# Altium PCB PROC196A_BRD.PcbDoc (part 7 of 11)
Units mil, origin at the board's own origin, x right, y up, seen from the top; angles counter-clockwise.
Board outline 3346.45 x 4921.26 mil, 8 copper layers (Top Layer, GND1, SIG1, PWR1, PWR2, SIG2, GND2, Bottom Layer), stack 54.534 mil thick; 736 components, 498 nets, 3030 pads, 1279 vias.
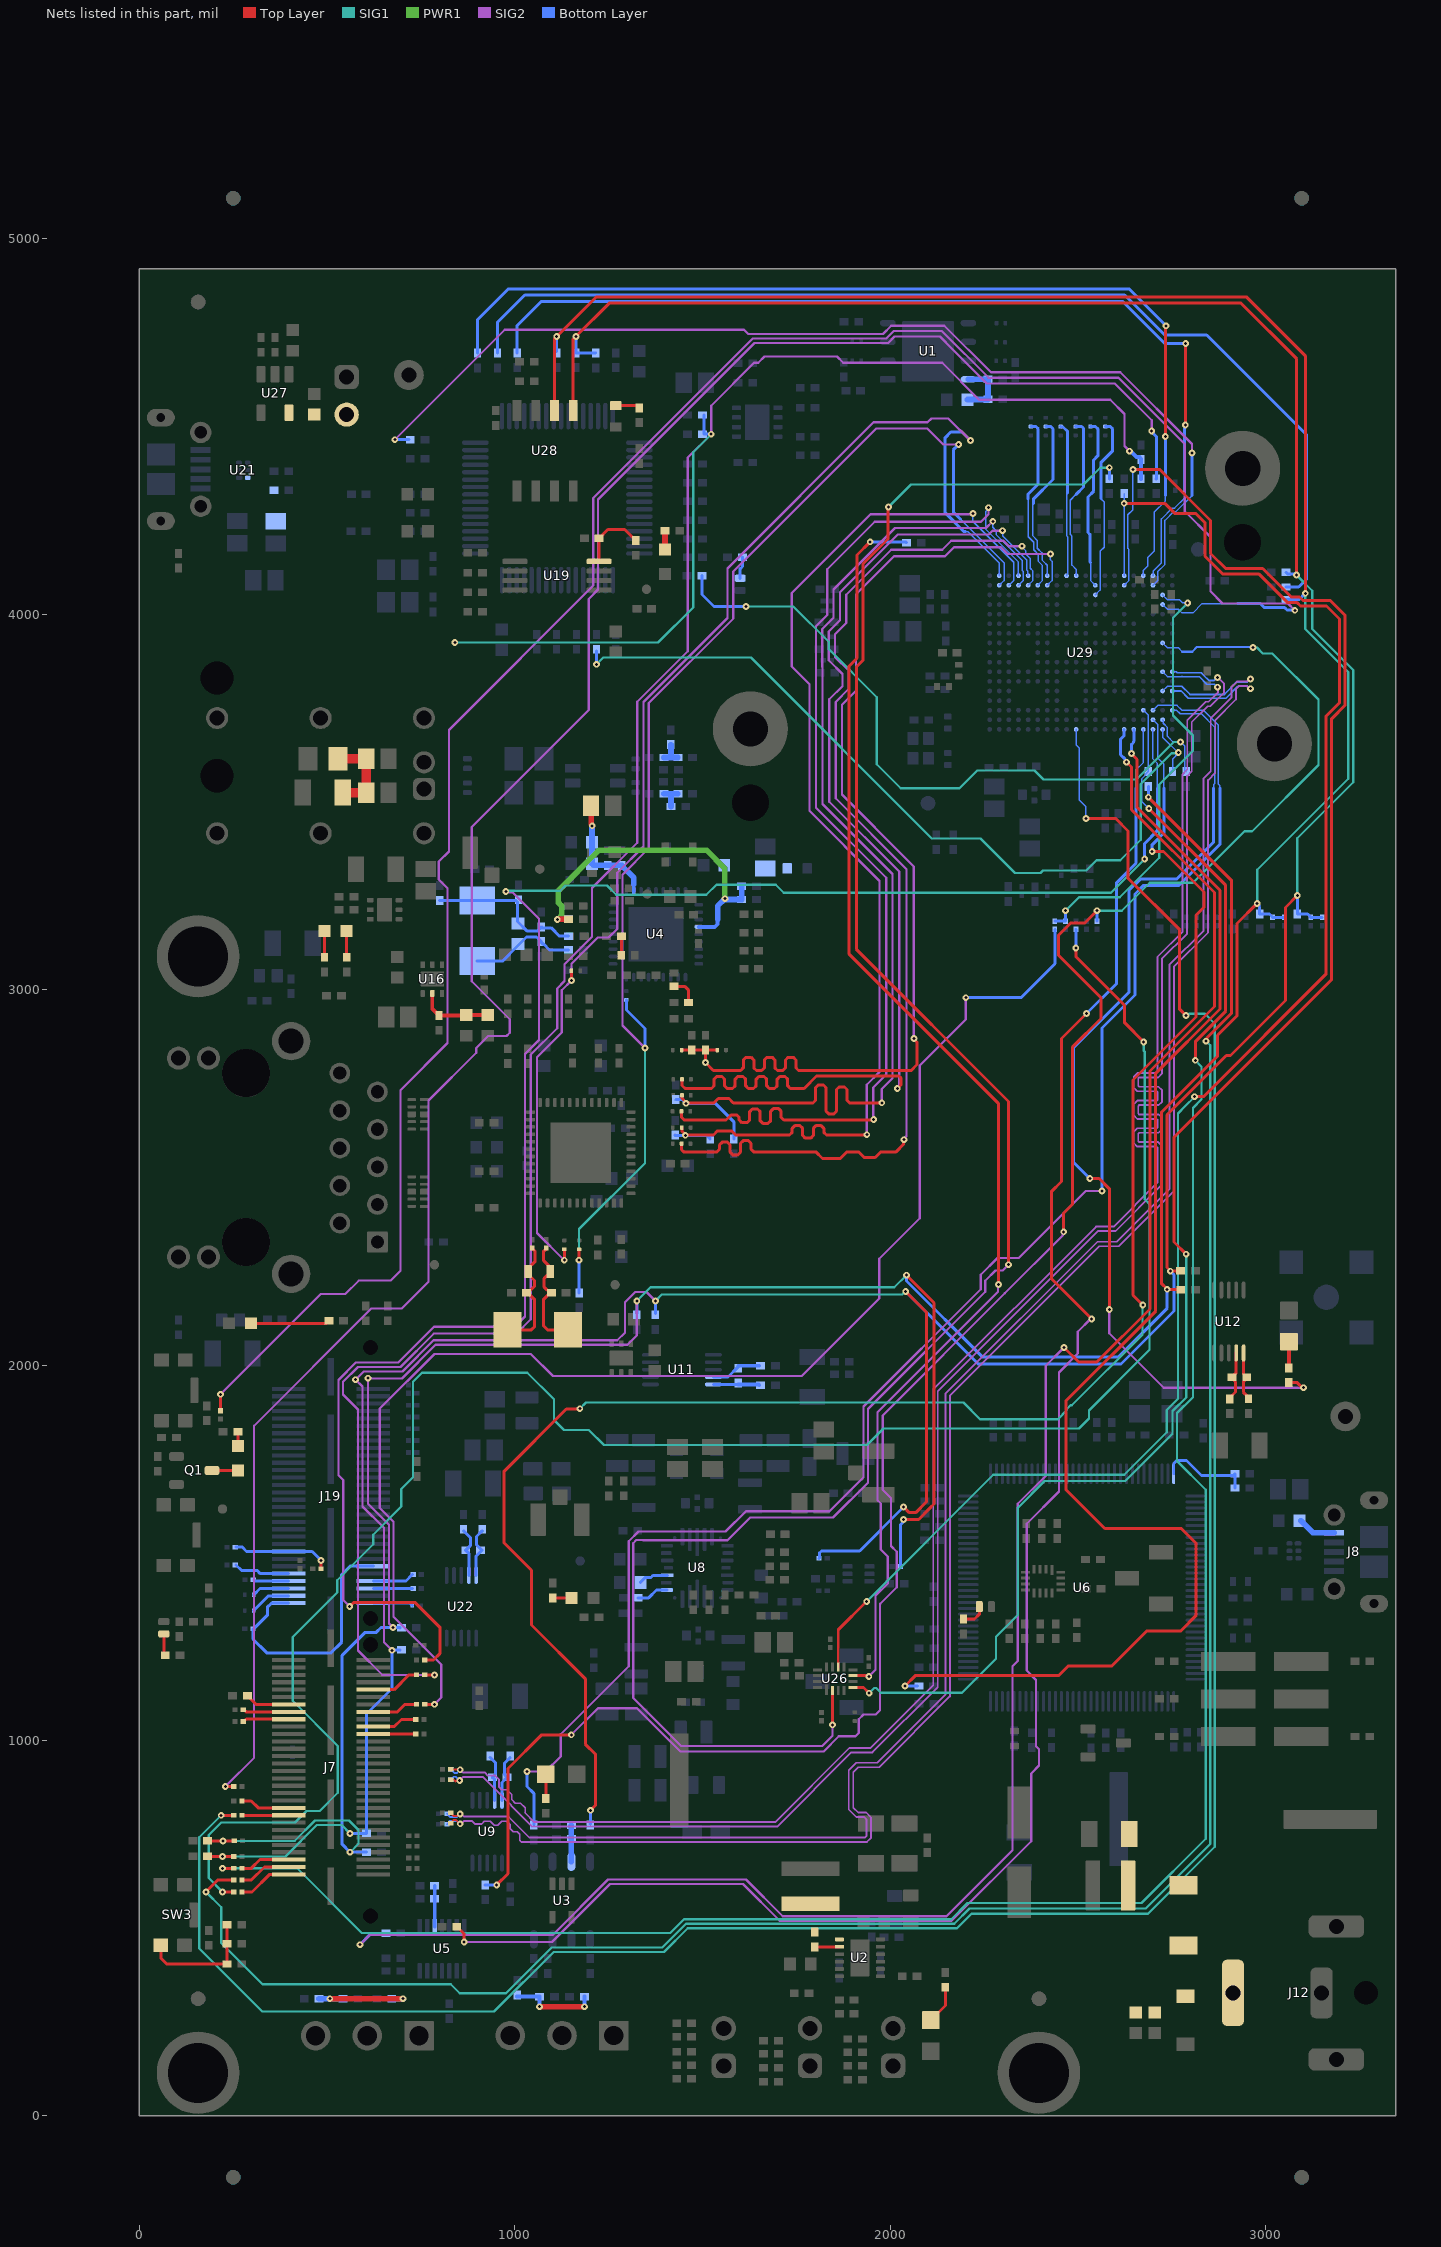
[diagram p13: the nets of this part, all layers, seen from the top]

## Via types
v1: diameter 18, hole 8, Top Layer to Bottom Layer, tented both sides, 1230 vias
v2: diameter 19.68, hole 7.87, Top Layer to Bottom Layer, 30 vias
v3: diameter 20, hole 10, Top Layer to Bottom Layer, tented both sides, 11 vias
v4: diameter 10, hole 4, SIG2 to Bottom Layer, tented both sides, 6 vias
v5: diameter 19.68, hole 7.87, Top Layer to Bottom Layer, tented both sides, 2 vias

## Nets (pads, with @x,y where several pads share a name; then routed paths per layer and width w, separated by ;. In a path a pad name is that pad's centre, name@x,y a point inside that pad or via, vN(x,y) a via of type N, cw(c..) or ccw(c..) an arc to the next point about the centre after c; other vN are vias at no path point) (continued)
LVDS_TX2_CLK_N: R349.2 R361.2 U29.E20 | length 5089.8
  Top Layer w4.8: R361.2@829.54,779.34 830.33,779.34 834.23,783.24 834.23,785.43 837.04,788.24 842.74,788.24 853.17,777.81 v1(854.61,777.81)
  SIG2 w4.8: v1(854.61,777.81) 857.02,777.81 864.21,785 886.91,785 894.91,777 911.52,777 919.33,784.81 935.08,784.81 945.69,774.21 954.77,774.21 965.37,784.81 978.7,784.81 987.74,775.78 987.74,764.91 995.65,757 1006.52,757 1013.22,750.3 1013.22,733.85 1017.57,729.5 1938.36,729.5 1948.79,739.94 1948.79,795.24 1936.03,808 1915.02,808 1902.02,821 1902.02,915.58 1915.13,928.7 1970.76,928.7 2159.35,1117.29 2159.35,1918.25 2557.5,2316.4 2609.02,2316.4 2756.03,2463.41 2756.03,3061.48 2847.08,3152.53 2847.08,3558.45 2866.22,3577.59 2866.22,3718.14 2921.29,3773.21 2921.29,3800.97 2929.15,3808.83 2950.62,3808.83 2957.62,3801.83 v1(2960.03,3801.83)
  Bottom Layer w4.8: R349.2@819.54,776.9 820.33,776.9 824.23,780.79 824.23,782.98 827.04,785.8 833.83,785.8 833.91,785.71 845.2,785.71 853.1,777.81 v1(854.61,777.81) ; U29.E20@2751.52,3795.89 2775.23,3795.89 2794.85,3776.27 2894.78,3776.27 2925.19,3806.67 2928.25,3809.73 2950.62,3809.73 2958.52,3801.83 v1(2960.03,3801.83)
LVDS_TX2_CLK_P: R345.2 R351.2 U29.E19 | length 5088.2
  Top Layer w4.8: R351.2@829.54,807.34 830.33,807.34 834.23,803.44 834.23,801.25 837.04,798.44 845.66,798.44 851.04,803.81 v1(854.61,803.81)
  SIG2 w4.8: v1(854.61,803.81) 857.66,803.81 864.02,797.45 983.04,797.45 1038.99,741.5 1933.39,741.5 1936.79,744.91 1936.79,790.27 1931.06,796 1910.05,796 1890.02,816.03 1890.02,920.55 1910.16,940.7 1965.79,940.7 2147.35,1122.26 2147.35,1923.22 2552.53,2328.4 2604.05,2328.4 2744.03,2468.38 2744.03,3066.45 2835.08,3157.5 2835.08,3563.42 2854.22,3582.56 2854.22,3723.11 2909.29,3778.18 2909.29,3805.94 2924.18,3820.83 2950.62,3820.83 2957.62,3827.83 v1(2960.03,3827.83)
  Bottom Layer w4: U29.E19@2725.93,3795.89 2738.65,3808.61 2763.22,3808.61
  Bottom Layer w4.8: R345.2@819.54,804.9 820.33,804.9 824.23,801 824.23,798.81 827.04,796 838.05,796 838.13,795.91 845.2,795.91 853.1,803.81 v1(854.61,803.81) ; 2763.22,3808.61 2776.93,3808.61 2799.07,3786.47 2890.56,3786.47 2924.03,3819.93 2925.19,3819.93 2950.62,3819.93 2958.52,3827.83 v1(2960.03,3827.83)
LVDS_TX3_FRCLK_N: R323.2 R341.2 U29.G20 | length 5061.1
  Top Layer w4.8: R341.2@832.81,891.74 837,895.93 841.82,891.11 841.97,891.11 842.48,890.59 845.12,893.23 v1(853.37,893.23)
  SIG2 w4.8: v1(853.37,893.23) 863.07,902.93 914.79,902.93 934.37,883.35 1047.12,770.6 1699.34,770.6 1896.74,968 1952.98,968 2127.14,1142.16 2127.14,1930.44 2553.7,2357 2600.41,2357 2724.02,2480.61 2724.02,2573.34 2724.02,2584.23 2714.18,2594.07 2663.42,2594.07 2660.94,2596.55 2660.94,2616.39 2663.42,2618.87 2715.12,2618.87 2724.63,2628.38 2724.63,2658.16 2715.12,2667.67 2663.42,2667.67 2660.94,2670.15 2660.94,2689.99 2663.42,2692.47 2715.12,2692.47 2724.63,2701.98 2724.63,2731.76 2715.12,2741.27 2663.42,2741.27 2660.94,2743.75 2660.94,2763.59 2663.42,2766.07 2714.18,2766.07 2724.02,2775.91 2724.02,2796 2724.02,3082.12 2791.23,3149.33 2791.23,3569.02 2803.83,3581.62 2803.83,3713.21 2845.73,3755.11 2853.22,3755.11 2889.89,3791.78 2889.89,3814.6 v1(2872.49,3832)
  Bottom Layer w4.8: R323.2@829.54,895.01 837.76,903.22 843.38,903.22 v1(853.37,893.23) ; U29.G20@2751.52,3847.07 2762.19,3847.07 2764.98,3844.27 2828.62,3844.27 2834.89,3838 2848.79,3824.1 2863.08,3824.1 2870.98,3832 v1(2872.49,3832) v1@2871.96,3831.47
LVDS_TX3_FRCLK_P: R322.2 R327.2 U29.G19 | length 5062.3
  Top Layer w4.8: R327.2@829.46,922.93 830.25,922.93 830.75,922.43 854.11,922.43 v1(854.61,921.93)
  SIG2 w4.8: v1(854.61,921.93) 861.61,914.93 899.66,914.93 919.76,914.93 928.33,906.35 947.63,906.35 957.71,896.27 957.71,876.98 965.95,868.73 979.37,868.73 992.1,856 992.1,842.79 992,842.69 1001.82,832.87 1015.32,832.87 1027.86,820.33 1027.86,807.78 1027.38,807.3 1052.09,782.6 1694.37,782.6 1891.77,980 1948.01,980 2115.14,1147.13 2115.14,1935.41 2548.73,2369 2595.44,2369 2712.02,2485.58 2712.02,2573.34 2712.02,2579.26 2709.21,2582.07 2658.45,2582.07 2648.94,2591.58 2648.94,2621.36 2658.45,2630.87 2710.15,2630.87 2712.63,2633.35 2712.63,2653.19 2710.15,2655.67 2658.45,2655.67 2648.94,2665.18 2648.94,2694.96 2658.45,2704.47 2710.15,2704.47 2712.63,2706.95 2712.63,2726.79 2710.15,2729.27 2658.45,2729.27 2648.94,2738.78 2648.94,2768.56 2658.45,2778.07 2709.21,2778.07 2712.02,2780.88 2712.02,2796 2712.02,3087.09 2779.23,3154.3 2779.23,3573.99 2791.83,3586.59 2791.83,3718.18 2840.76,3767.11 2848.25,3767.11 2873.75,3792.61 2873.75,3804.74 v1(2872.49,3806)
  Bottom Layer w4: U29.G19@2725.93,3847.07 2738.8,3834.2 2777.55,3834.2 2777.67,3834.07
  Bottom Layer w4.8: R322.2@829.46,922.93 838.96,913.42 846.11,913.42 v1(854.61,921.93) ; 2777.67,3834.07 2778.07,3833.67 2824.22,3833.67 2844,3813.9 2863.08,3813.9 2870.98,3806 v1(2872.49,3806)
MCU_CLK_OUT: R165.1 R216.1 U29.R19 | length 1198.4
  SIG1 w6: v1(2467,3210.52) 2503.1,3246.62 2611.96,3246.62 2717.05,3351.71 2717.05,3536.81 2717.05,3546.92 2806.96,3636.83 2806.96,3676.99 2777.67,3706.28 2753.57,3730.38 2753.57,3991.05 v1(2792.89,4030.37)
  Bottom Layer w4: U29.R19@2725.93,4051.79 2738.76,4038.96 2770.86,4038.96 2779.45,4030.37 v1(2792.89,4030.37) v1@2796.89,4030.37
  Bottom Layer w8: R165.1@2439,3182.81 R216.1@2467,3182.81 v1(2467,3210.52)
MCU_CLKOUT: R115.1 R165.2 | length 3653.8
  Top Layer w8: R115.1@760.24,1096.36 v1(786.39,1096.36)
  SIG2 w6: v1(786.39,1096.36) 804.39,1114.36 804.39,1202.13 677.21,1329.31 677.21,1582.74 640.44,1619.51 640.44,1884.22 786.03,2029.81 1043,2029.81 1102,1970.81 1764.81,1970.81 1971.14,2177.14 1971.14,2282.99 2079,2390.85 2079,2798 2201.8,2920.8 v1(2201.8,2978.71)
  Bottom Layer w8: v1(2201.8,2978.71) 2348.61,2978.71 2439.12,3069.22 2439.12,3160.64 R165.2@2439,3160.76
MIPI_DBG_DETECT: J19.15 R226.2 R321.2 | length 263.6
  Top Layer w8: R226.2@484,1457.42 v1@484,1479.65
  Bottom Layer w8: R321.2@257.44,1514.71 274.46,1514.71 285.68,1503.49 J19.15@397.49,1503.49 460.54,1503.49 484.04,1479.99 v1(484.04,1479.68)
MIPI_JTAG_NRST: J19.9 R508.2 | length 149.7
  Bottom Layer w8: R508.2@257.44,1467.61 271.89,1453.16 313.33,1453.16 322.05,1444.44 J19.9@397.49,1444.44
MIPI_NRST: J19.6 R243.1 | length 104.2
  Bottom Layer w8: J19.6@623.08,1405.07 R243.1@727.27,1405.07
MIPI_RTCK: J19.7 R244.2 | length 93.1
  Bottom Layer w8: R244.2@305.65,1427.81 308.71,1424.75 J19.7@397.49,1424.75
MIPI_TCK: J19.3 R375.1 | length 109.2
  Bottom Layer w8: R375.1@304.64,1346.03 343.99,1385.38 J19.3@397.49,1385.38
MIPI_TDI: J19.5 R376.1 | length 99.9
  Bottom Layer w8: R376.1@304.64,1388.1 321.61,1405.07 J19.5@397.49,1405.07
MIPI_TMS: J19.2 R374.2 | length 106.6
  Bottom Layer w8: J19.2@623.08,1365.7 720.99,1365.7 R374.2@727.13,1359.56
MIPI_TRSTPD: J19.8 R512.1 | length 111.3
  Bottom Layer w8: J19.8@623.08,1424.75 710.12,1424.75 R512.1@727.3,1441.92
MIPI_VREF_DEBUG: J19.1 J19.12 R503.2 | length 697.2
  Bottom Layer w8: R503.2@302.91,1297.35 302.91,1269.88 339.35,1233.45 510.58,1233.45 538.82,1261.69 538.82,1441.67 561.27,1464.12 J19.12@623.08,1464.12 ; R503.2@304.88,1297.35 340.93,1333.4 340.93,1354.85 351.78,1365.7 J19.1@397.49,1365.7
MSS_EPWMA0: R81.1 U29.A18 | length 4905.5
  Top Layer w8: v1(560.23,1356.92) 570.31,1367 735.25,1367 800.49,1301.76 800.49,1231.06 783.47,1214.04 R81.1@760.24,1214.04
  SIG1 w6: v1(976.32,3261.66) 978.57,3263.91 1121.09,3263.91 1135,3277.81 1245.53,3277.81 1270.53,3252.81 1510.27,3252.81 1537.27,3279.81 1695.53,3279.81 1716.72,3258.62 2588.39,3258.62 v1(2678.14,3348.37)
  SIG2 w6: v1(560.23,1356.92) 543.27,1373.88 543.27,1694.04 530.65,1706.66 530.65,1960.46 577.39,2007.2 690.57,2007.2 785.18,2101.81 999.8,2101.81 1027.57,2129.58 1027.57,2828.76 1064.65,2865.85 1064.65,3189.19 994.32,3259.52 978.46,3259.52 v1(976.32,3261.66)
  Bottom Layer w4: U29.A18@2700.34,3693.52 2700.34,3614.66 2712,3603 2712,3536.81
  Bottom Layer w8: v1(2678.14,3348.37) 2678.14,3389.57 2712,3423.43 2712,3536.81
MSS_EPWMA1: R198.1 R213.2 | length 6034.8
  Top Layer w8: v1(177.19,596.46) 208.69,627.95 R198.1@249.35,627.95 ; v1(2688,3512.81) 2909,3291.81 2909,2936.45 2843.77,2871.22 2843.77,2864.91 v1(2841.86,2863)
  SIG1 w6: v1(177.19,596.46) 218.08,555.57 218.08,460.07 327.93,350.23 829.72,350.23 853.17,326.77 976.78,326.77 1098.68,448.66 1392.94,448.66 1456.12,511.84 2170.88,511.84 2211.54,552.5 2681.26,552.5 2853,724.24 2853,1010.67 2853,1639.81 2853,2851.86 v1(2841.86,2863)
  Bottom Layer w8: R213.2@2687.85,3541.71 2687.93,3541.64 2687.93,3512.88 v1(2688,3512.81)
MSS_EPWMB0: R197.1 R213.1 U29.C17 | length 6033.5
  Top Layer w8: v1(221.63,659.45) R197.1@249.35,659.45 ; v1(2689.2,3483.04) 2894,3278.24 2894,2942.66 2813,2861.66 v1(2813,2812)
  SIG1 w6: v1(221.63,659.45) 420.3,659.45 592.48,487.27 1414.58,487.27 1451.15,523.84 2163.26,523.84 2206.14,566.72 2669.95,566.72 2841,737.78 2841,1667.97 2764.58,1744.4 2764.58,1872.39 2806.68,1914.49 2806.68,2684.94 2829.28,2707.54 2829.28,2795.72 v1(2813,2812)
  Bottom Layer w4: U29.C17@2674.75,3744.7 2687.62,3731.83 2687.62,3581.32 R213.1@2687.85,3581.08 2680.77,3574 2680.77,3572.03 2670.01,3561.27 2670.01,3502.23 v1(2689.2,3483.04)
MSS_GPIO_1: R329.1 U29.A10 | length 6580.9
  Top Layer w8: v1(218.08,800.66) R329.1@249.37,800.66 ; v1(2521.67,3456) 2600.92,3456 2634.06,3422.86 2634.06,3296.84 2771.32,3159.58 2771.32,2947.8 v1(2788.12,2931)
  SIG1 w6: v1(218.08,800.66) 159.19,741.77 159.19,445.88 327.12,277.95 944.93,277.95 1103.65,436.66 1397.91,436.66 1461.09,499.84 2178.53,499.84 2216.87,538.18 2686.86,538.18 2865.17,716.49 2865.17,2909.64 2838.81,2936 2796.37,2936 2791.37,2931 v1(2788.12,2931)
  Bottom Layer w4: U29.A10@2495.62,3693.52 2495.62,3652.72 2504.17,3644.17 2504.17,3505.11 2521.67,3487.61 v1(2521.67,3456)
MSS_GPIO_2: R347.2 U29.C20 | length 2634.5
  Top Layer w8: v1(2531.9,2497) 2557.06,2497 2584.1,2469.96 v1(2584.1,2148) ; R347.2@3062.49,1953.11 3085,1953.11 3098.29,1939.81 v1(3101,1939.81)
  SIG2 w6: v1(2584.1,2148) 2584.1,2084.71 2729,1939.81 v1(3101,1939.81)
  Bottom Layer w4: U29.C20@2751.52,3744.7 2763.11,3744.7 2772.81,3735 2777.67,3735 2829.71,3735 2864.45,3700.26 2864.45,3549.11 2861.95,3546.61 2861.95,3536.81
  Bottom Layer w8: v1(2531.9,2497) 2488.17,2540.73 2488.17,2844.7 2636.1,2992.64 2636.1,3264.07 2666.54,3294.51 2762.75,3294.51 2861.95,3393.71 2861.95,3536.81
MSS_GPIO_3: R114.1 R219.2 | length 5266.8
  Top Layer w8: v1(221.63,596.46) R114.1@249.35,596.46 ; v1(2494.71,3111.3) 2494.71,3088.18 2624.94,2957.95 2624.94,2911.8 v1(2675.74,2861)
  SIG1 w6: v1(221.63,596.46) 184.83,633.25 184.83,748.37 217.97,781.51 414.72,781.51 445.4,812.19 480.49,812.19 528.78,860.48 528.78,985.24 408.37,1105.66 408.37,1275.73 526.92,1394.28 526.92,1426.72 623.02,1522.82 623.02,1548.18 698,1623.16 698,1670.15 728.99,1701.14 728.99,1955.8 753,1979.81 1033.6,1979.81 1104.72,1908.69 1104.72,1853.92 1131.32,1827.31 1197.39,1827.31 1237.7,1787 1938.73,1787 1982.62,1830.89 2503.07,1830.89 2529.6,1857.41 2529.6,1879.01 2691.33,2040.74 2691.33,2429.21 2678.7,2441.84 2678.7,2834.5 2675.74,2837.46 v1(2675.74,2861)
  Bottom Layer w8: v1(2494.71,3111.3) 2494.86,3111.44 2494.86,3160.62 R219.2@2495,3160.76
MSS_GPIO_11: R54.1 R236.2 U29.K19 | length 5482.2
  Top Layer w8: v1(951.98,615.22) 981.93,645.17 981.93,924.98 1071.95,1015 v1(1150.85,1015) ; v1(2462.42,2354.97) 2462.42,2405.08 2486.49,2429.15 2486.49,2847.78 2561.84,2923.13 2561.84,2978.63 2449.11,3091.35 2449.11,3144.27 2449.11,3145.97 2480.41,3177.26 2517.74,3177.26 v1(2551,3210.52)
  SIG1 w6: v1(2551,3210.52) 2616.99,3210.52 2691.47,3285 2807.18,3285 2944.33,3422.15 2964.46,3422.15 3141.04,3598.73 3141.04,3773.23 3018.42,3895.85 2993.02,3895.85 2977.49,3911.38 2967.23,3911.38 v1(2966.61,3912)
  SIG2 w6: v1(1150.85,1015) 1221.85,1086 1325.78,1086 1441.08,970.7 1823.23,970.7 1863.53,1011 1907.77,1011 1916.56,1019.79 1916.56,1056.28 1929.28,1069 1961.99,1069 1973.39,1080.4 1973.39,1364.43 1973.6,1364.43 2017.6,1408.44 2017.6,1502.36 2002.22,1517.75 2002.22,1645.35 1980.21,1667.36 1980.21,1865.57 2305.68,2191.04 2460.12,2345.48 2460.12,2352.68 v1(2462.42,2354.97)
  Bottom Layer w4: U29.K19@2725.93,3923.84 2738.76,3911.01 2744.66,3911.01 2767.95,3911.01 2777.67,3901.29
  Bottom Layer w6: 2777.67,3901.29 2778.46,3900.49 2804.73,3900.49 2817.24,3913 2965.61,3913 v1(2966.61,3912)
  Bottom Layer w8: R54.1@921.27,615.22 v1(951.98,615.22) ; R236.2@2551,3182.81 v1(2551,3210.52)
MSS_GPIO_28: R334.2 U29.P19 | length 5881.1
  Top Layer w8: R334.2@215.95,1878.47 216.06,1878.58 216.06,1922 v1(216.17,1922.12)
  SIG2 w6: v1(216.17,1922.12) 483.34,2189.29 548.64,2189.29 584.35,2225 669.01,2225 696,2251.99 696,2732.85 821.08,2857.93 821.08,3270.35 797.69,3293.74 797.69,3341.52 824.62,3368.45 824.62,3692.2 1209,4076.58 1209,4309.85 1634.01,4734.86 1989.89,4734.86 2010.03,4755 2137.81,4755 2262.5,4630.31 2608.64,4630.31 2785,4453.95 2785,4274.75 2853.39,4206.36 2853.39,4061.42 2885.6,4029.21 3059.86,4029.21 v1(3078.26,4010.81)
  Bottom Layer w4: U29.P19@2725.93,4026.2 2738.8,4013.33 2767.9,4013.33 2777.36,4003.87 2806.57,4003.87 2831.3,4028.6 2925.19,4028.6
  Bottom Layer w7.61: 3037.57,4018.1 3050.92,4018.1 3051.12,4017.91
  Bottom Layer w8: 2925.19,4028.6 2986.62,4028.6 2997.31,4017.91 3031.13,4017.91 3031.32,4018.1 3037.57,4018.1 ; 3051.12,4017.91 3057.26,4011.76 3077.31,4011.76 v1(3078.26,4010.81)
MSS_I2CA_SCL: R3.1 R23.2 R27.2 R33.2 R57.2 R58.2 R148.2 R229.1 R231.2 R276.1 R318.1 R390.1 U28.6 | length 10666.3
  Top Layer w8: R276.1@185.75,732.43 v1(222.91,732.43) R390.1@250.63,732.43 ; U28.6@1105.83,4543.13 1105.83,4734.27 v1(1111.81,4740.26) 1216.36,4844.81 2950.19,4844.81 3106.27,4688.73 v1(3106.27,4056) ; v1(2036,1588.81) 2076,1588.81 2107,1619.81 2117,1629.81 2117,2165.81 v1(2043.48,2239.33) ; R58.2@2774.48,2200.17 2773.57,2201.09 2739.18,2201.09 2722.42,2217.85 2722.42,2672.81 2872.27,2822.66 2872.27,2878.5 2924.16,2930.39 2924.16,3176.2 v1(2977.96,3230)
  SIG1 w6: v1(222.91,732.43) 413.73,732.43 467.77,786.47 558.52,786.47 583.89,761.1 583.89,724.54 v1@561.51,702.16 ; v1(1325.38,2170.91) 1361.55,2207.07 2011.22,2207.07 v1(2043.48,2239.33) ; v1(2977.96,3230) 2977.96,3319.4 3220.87,3562.31 3220.87,3846.18 3106.27,3960.78 v1(3106.27,4056)
  SIG2 w6: v1(675.87,1300.65) 665.21,1311.31 665.21,1574.6 609.21,1630.6 v1(609.21,1965.2) 610.25,1964.16 699.41,1964.16 789.2,2053.95 1300.14,2053.95 1325,2078.81 1325,2170.53 v1(1325.38,2170.91)
  Bottom Layer w8: R27.2@605.2,702.16 561.41,702.16 540.27,723.3 540.27,1226.73 601.64,1288.1 631.17,1288.1 643.72,1300.65 v1(675.87,1300.65) 676.09,1300.43 693.96,1300.43 R57.2@694.18,1300.21 ; R148.2@1111.81,4700.64 v1(1111.81,4740.26) ; R33.2@1325.38,2137.94 v1(1325.38,2170.91) ; R318.1@2027.72,1463.53 2027.72,1574.9 2034.14,1581.33 2034.14,1586.95 v1(2036,1588.81) ; v1(2043.48,2239.33) 2043.48,2224.22 2245.7,2022 2608.54,2022 2738.27,2151.73 v1(2738.27,2202) ; v1(2977.96,3230) 2977.96,3227.62 2984.64,3220.94 2984.64,3201.81 R23.2@2984.98,3201.47 3011.03,3201.47 3018.9,3193.6 R229.1@3018.9,3192.81 R231.2@3050,3192.81 ; R3.1@3054.13,4038.75 3055.23,4039.85 3090.12,4039.85 v1(3106.27,4056)
  other v1: 561.37,702.16
MSS_I2CA_SDA: R22.2 R29.2 R31.1 R35.2 R59.2 R62.2 R149.2 R150.2 R224.1 R227.2 R277.1 R319.2 R391.1 U28.5 | length 10567.8
  Top Layer w8: R277.1@185.75,691.43 186.23,690.95 v1(221.63,690.95) R391.1@249.35,690.95 ; U28.5@1155.83,4543.13 1155.83,4733.2 v1(1162.88,4740.26) 1251.63,4829 2934.81,4829 3083,4680.81 v1(3083,4104.81) ; v1(2035.9,1621.85) 2036.16,1621.85 2051.19,1606.81 2068,1606.81 2096.93,1635.74 2096.93,2140.88 v1(2041.61,2196.2) ; R59.2@2774.1,2251 2773.6,2250.5 2747.1,2250.5 v1(2746.6,2250) 2746.6,2250.51 2737.42,2259.69 2737.42,2666.6 2895.85,2825.03 2906.88,2825.03 3053.15,2971.29 3053.15,3218.96 v1(3085,3250.81)
  SIG1 w6: v1(221.63,690.95) 389.22,690.95 472.74,774.47 539.1,774.47 v1(561.37,752.2) ; v1(1374.75,2170.91) 1391.75,2187.91 2032.1,2187.91 2040.39,2196.2 v1(2041.61,2196.2) ; v1(3083,4104.81) 3124.96,4062.85 3124.96,3960.73 3233.98,3851.71 3233.98,3552.69 3085,3403.71 v1(3085,3250.81)
  SIG2 w6: v1(673.26,1240.08) 651.44,1261.91 651.44,1566.37 594.33,1623.48 594.33,1942.63 v1(575.81,1961.14) 597.87,1983.2 700.83,1983.2 783.58,2065.95 1273.14,2065.95 1293.5,2086.31 1293.5,2167.31 1320.85,2194.67 1350.99,2194.67 v1(1374.75,2170.91)
  Bottom Layer w5.5: v1@561.27,752.2 v1@561.56,752.49
  Bottom Layer w8: v1@561.27,752.2 v1(561.37,752.2) 605.05,752.2 R29.2@605.34,752.49 605.34,1070.68 673.26,1138.61 v1(673.26,1240.08) 673.8,1240.62 693.64,1240.62 R62.2@694.18,1241.15 ; R149.2@1162.88,4696.7 1215.08,4696.7 R150.2@1215.81,4695.97 ; R149.2@1162.88,4700.64 v1(1162.88,4740.26) ; R35.2@1374.75,2137.94 v1(1374.75,2170.91) ; R319.2@1810.74,1485.22 1811.27,1485.75 1811.27,1499.08 1817.03,1504.84 1918.89,1504.84 v1(2035.9,1621.85) ; v1(2041.61,2196.2) 2234.81,2003 2615.29,2003 2756.27,2143.98 2756.27,2240.31 v1(2746.6,2250) ; R31.1@3054.85,4111.81 3059.03,4107.63 3077.56,4107.63 3080.38,4104.81 v1(3083,4104.81) ; v1(3085,3250.81) R22.2@3085,3201.47 3112.61,3201.47 3120.48,3193.6 R224.1@3120.48,3192.81 R227.2@3151,3192.81
MSS_MCANA_RX: R12.1 U29.B18 | length 4764.9
  Top Layer w8: v1(1173.44,1883.81) 1172.44,1882.81 1137.32,1882.81 972,1717.49 972,1526.18 1044.88,1453.3 1044.88,1307.32 1188,1164.2 1188,990.09 1215.78,962.31 1215.78,828.04 v1(1201.74,814) ; v1(2673.33,2160) 2646.98,2186.35 2646.98,2759.28 2814.88,2927.18 2814.88,3198.2 2836.11,3219.43 2836.11,3260.51 2728.64,3367.98 v1(2698.33,3367.98)
  SIG1 w6: v1(1173.44,1883.81) 1189.63,1900 2195.32,1900 2239.51,1855.81 2447.12,1855.81 2470,1878.69 2470,1882.27 2480.54,1892.81 2484.12,1892.81 2672.19,2080.88 2672.19,2158.86 v1(2673.33,2160)
  Bottom Layer w4: U29.B18@2700.34,3719.11 2713.06,3706.39 2713.06,3661.86 2713.06,3658.75 2713.06,3617.28 2729.44,3600.9 2729.44,3536.81
  Bottom Layer w8: R12.1@1200.93,776.96 1201.33,777.37 1201.33,813.59 v1(1201.74,814) ; v1(2698.33,3367.98) 2698.26,3368.05 2698.26,3386.52 2729.44,3417.7 2729.44,3536.81
MSS_MCANA_TX: R11.1 U29.C18 | length 4313.7
  SIG2 w6: v1(1032.65,917) 1082.19,917 1122.63,957.44 1122.63,1016.63 1303.44,1197.44 1303.44,1530.44 1329.5,1556.5 1561.5,1556.5 1615.85,1610.85 1838.29,1610.85 1928.84,1701.4 1928.84,1889.35 2241.37,2201.88 2241.37,2240.45 2286.32,2285.4 2342.92,2285.4 2521.52,2464 v1(2564.6,2464)
  Bottom Layer w4: U29.C18@2700.34,3744.7 2713.06,3757.43 2764.38,3757.43 2777.31,3744.5 2834.59,3744.5 2874.25,3704.84 2874.25,3547.9 2878.25,3543.9 2878.25,3536.81
  Bottom Layer w8: v1(1032.65,917) 1032.65,877.54 1050.93,859.26 R11.1@1050.93,774.4 ; v1(2564.6,2464) 2564.6,2898.08 2652.4,2985.88 2652.4,3254.96 2675.65,3278.21 2769.5,3278.21 2878.25,3386.96 2878.25,3536.81
MSS_MCANB_RX: R25.1 U29.A17 | length 4957
  Top Layer w8: R25.1@845.68,503.91 847.64,503.91 853.49,498.07 853.49,496.1 865.4,484.19 v1(865.4,463.27) ; v1(2523.36,2936.68) 2456.49,2869.82 2456.49,2488.84 2429.42,2461.77 2429.42,2230.47 v1(2537.05,2122.85)
  SIG2 w6: v1(865.4,463.27) 1099.49,463.27 1253.75,617.54 1608.09,617.54 1706.29,519.33 2163.52,519.33 2375.74,731.55 2375.74,911.78 2397,933.03 2397,976.47 2388.98,984.49 2388.98,1161.33 2363.93,1186.38 2363.93,1384.34 2364,1384.41 2364,1419.21 2363.93,1419.28 2363.93,1577.19 2449.74,1663.01 2449.74,1980.33 2500.25,2030.84 2500.25,2089.02 2534.07,2122.85 v1(2537.05,2122.85)
  Bottom Layer w4: 2655.3,3536.81 2655.3,3586.11 2674.75,3605.56 U29.A17@2674.75,3693.52
  Bottom Layer w8: v1(2523.36,2936.68) 2603.5,3016.82 2603.5,3285.26 2655.3,3337.06 2655.3,3536.81
MSS_MCANB_TX: R21.1 U29.A15 | length 5429.2
  Top Layer w8: v1(2463.51,2047) 2502.51,2008 2550.74,2008 2692.42,2149.68 2692.42,2783.51 2864,2955.09 2864,3258.7 2643,3479.7 2643,3536.81 2643,3593.36 v1(2630.07,3606.29)
  SIG2 w6: v1(587.53,455.73) 614.24,482.44 1101.69,482.44 1248.78,629.54 1615.8,629.54 1714,531.33 2150.02,531.33 2326.16,707.48 2326.16,1197.91 2339.93,1211.68 2339.93,1394.28 2340,1394.35 2340,1409.27 2339.93,1409.34 2339.93,1630.3 2414.4,1704.77 2414.4,1997.89 v1(2463.51,2047)
  Bottom Layer w8: v1(587.53,455.73) 618,486.19 R21.1@657.14,486.19 ; U29.A15@2623.57,3693.52 2623.57,3677.07 2613.9,3667.4 2613.9,3661.87 2613.9,3658.75 2613.9,3626.06 2625,3614.96 2625,3614.07 2630,3609.07 2630.07,3609 v1(2630.07,3606.29)
MSS_MDIO_CLK: R249.1 R369.1 U29.U2 | length 3508.9
  Top Layer w8: v1(1132.04,2279.28) R369.1@1132.04,2308.19 ; R249.1@1150.95,3050.42 1150.95,3028.46 1151.06,3028.35 v1(1151.06,3024.41)
  SIG2 w6: v1(1132.04,2279.28) 1059.46,2351.86 1059.46,2820.27 1125.2,2886.01 1125.2,2998.55 v1(1151.06,3024.41) 1151.06,3068.9 1220.97,3138.81 1250,3138.81 1273,3161.81 1273,3311.81 1343,3381.81 1343,3766.6 1566.58,3990.18 1566.58,4122.41 1955.98,4511.81 2099.88,4511.81 2110.07,4522 2155,4522 v1(2214,4463)
  Bottom Layer w4: 2201,4220.31 2207.54,4220.31 2290.89,4136.96 U29.U2@2290.89,4102.97
  Bottom Layer w8: 2201,4220.31 2197,4220.31 2146.85,4270.47 2146.85,4387.18 2146.85,4470.8 2161.59,4485.55 2191.45,4485.55 v1(2214,4463)
MSS_MDIO_DATA: R247.1 R280.1 R413.1 U29.T2 | length 3536.5
  Top Layer w8: v1(1171.49,2279.28) R413.1@1171.49,2308.19
  SIG1 w6: v1(1171.49,2279.28) 1171.49,2362.46 1346.93,2537.89 v1(1346.93,2845.01)
  SIG2 w6: v1(1346.93,2845.01) 1287,2904.94 1287,3306.61 1357.07,3376.68 1357.07,3763.7 1582,3988.63 1582,4113.9 1963.1,4495 2099.01,4495 2141.53,4452.49 v1(2182.59,4452.49)
  Bottom Layer w4: 2187.74,4253.55 2303.61,4137.67 2303.61,4090.1 U29.T2@2290.89,4077.38
  Bottom Layer w8: R280.1@1171.49,2192.39 v1(1171.49,2279.28) ; R247.1@1297.46,2972.72 1297.46,2947.46 1297.67,2947.25 1297.67,2946.07 1346.93,2896.81 v1(1346.93,2845.01) ; v1(2182.59,4452.49) 2168.57,4438.47 2168.57,4387.18 2168.57,4272.72 2187.74,4253.55
MSS_RGMII_RCLK: R234.1 R290.1 U29.T5 | length 2981.8
  Top Layer w8: R290.1@1444.53,2590.02 1444.53,2573.69 1450.02,2568.2 1532,2568.2 1538.56,2568.2 1545.56,2575.2 1545.56,2586.68 1552.56,2593.68 1566.56,2593.68 1573.56,2586.68 1573.56,2567.27 1580.56,2560.27 1594.56,2560.27 1601.56,2567.27 1601.56,2590.93 1608.56,2597.93 1622.56,2597.93 1629.56,2590.93 1629.56,2575.2 1636.56,2568.2 1668.56,2568.2 1802,2568.2 1819.78,2550.42 1867.22,2550.42 1885,2568.2 1915.84,2568.2 1931.04,2553 1960.36,2553 1975.56,2568.2 2016.2,2568.2 2036,2588 2036,2599.42 v1(2037.14,2600.56)
  SIG2 w6: v1(2037.14,2600.56) 2037.14,2603.51 2043.7,2610.07 2043.7,3321.11 1855,3509.81 1855,3766.48 1890,3801.48 1890,3849.43 1853.29,3886.13 1853.29,3946.97 1883.28,3976.96 1883.28,4052.1 2002.98,4171.81 2138.96,4171.81 2163.15,4196 2302.35,4196 2316.7,4181.65 v1(2351.28,4181.65)
  Bottom Layer w4: v1(2351.28,4181.65) 2351.28,4179.32 2360.73,4169.88 2360.73,4161.6 2373.28,4149.04 2373.28,4138.07 2373.28,4127.7 2373.28,4122.62 2380.38,4115.52 2380.38,4090.1 U29.T5@2367.66,4077.38
MSS_RGMII_RCTL: R195.1 R211.1 R245.1 R289.2 U29.T7 | length 2886.3
  Top Layer w8: R195.1@1444.84,2839.29 R211.1@1471.91,2839.29 R289.2@1508.33,2839.29 ; v1(1508.36,2805.87) R289.2@1508.33,2839.29 ; v1(1508.36,2805.87) 1529.2,2785.02 1598.05,2785.02 1602.05,2785.02 1609.05,2792.02 1609.05,2812.72 1616.05,2819.72 1630.05,2819.72 1637.05,2812.72 1637.05,2791.7 1644.05,2784.7 1658.05,2784.7 1665.05,2791.7 1665.05,2812.8 1672.05,2819.8 1686.05,2819.8 1693.05,2812.8 1693.05,2791.77 1700.05,2784.77 1714.05,2784.77 1721.05,2791.77 1721.05,2812.87 1728.05,2819.87 1742.05,2819.87 1749.05,2812.87 1749.05,2792.02 1756.05,2785.02 1885.73,2785.02 2056.42,2785.02 2071.94,2800.54 2071.94,2860.31 2063.58,2868.67 v1(2063.58,2870) ; R245.1@1539.21,2839.29 R289.2@1508.33,2839.29
  SIG2 w6: v1(2063.58,2870) 2063.25,2870.33 2063.25,3323.56 2063.25,3328.56 2050,3341.81 1872,3519.81 1872,3759.44 1909,3796.44 1909,4053.28 2010.53,4154.81 2146,4154.81 2170.19,4179 2295.31,4179 2313.31,4161 v1(2427,4161)
  Bottom Layer w4: U29.T7@2418.84,4077.38 2431.6,4090.14 2431.6,4127.7 2431.6,4141.1 2427,4145.71 v1(2427,4161)
MSS_RGMII_RD0: R173.1 R237.1 R287.2 R325.1 U29.T3 | length 3065.5
  Top Layer w8: R325.1@1444.84,2632.81 1445.22,2632.43 1445.22,2623.41 1454.58,2614.04 v1(1454.58,2612.04) ; v1@1455.47,2612.93 1529.26,2612.93 1540.33,2624 1577.49,2624 1588.57,2612.93 1728.28,2612.93 1732.28,2612.93 1739.28,2619.93 1739.28,2630.81 1746.28,2637.81 1760.28,2637.81 1767.28,2630.81 1767.28,2611.37 1774.28,2604.37 1788.28,2604.37 1795.28,2611.37 1795.28,2630.81 1802.28,2637.81 1816.28,2637.81 1823.28,2630.81 1823.28,2619.93 1830.28,2612.93 1888,2612.93 1937.12,2612.93 v1(1938,2613.81)
  SIG2 w6: v1(1938,2613.81) 1938,2746.64 1971.98,2780.62 1971.98,3289.87 1785.29,3476.56 1785.29,3813.57 1738.05,3860.81 1738.05,4056.86 1948,4266.81 2218.79,4266.81 v1(2220.79,4268.81)
  Bottom Layer w4: v1(2220.79,4268.81) 2220.17,4268.19 2220.17,4247.99 2329.2,4138.95 2329.2,4090.1 U29.T3@2316.48,4077.38
  Bottom Layer w8: R173.1@1427.4,2612.48 1427.62,2612.26 1454.36,2612.26 v1(1454.58,2612.04) 1511.68,2612.04 1520.83,2602.89 R287.2@1520.83,2602.23
MSS_RGMII_RD1: R238.1 R336.1 U29.U4 | length 2960
  Top Layer w8: R336.1@1444.11,2676.49 1444.11,2660.15 1451.46,2652.81 1553,2652.81 1563.01,2652.81 1570.01,2659.81 1577.01,2666.81 1591.01,2666.81 1598.01,2659.81 1598.01,2652.81 1605.01,2645.81 1619.01,2645.81 1626.01,2652.81 1626.01,2675.17 1633.01,2682.17 1647.01,2682.17 1654.01,2675.17 1654.01,2650.9 1661.01,2643.9 1675.01,2643.9 1682.01,2650.9 1682.01,2676.17 1689.01,2683.17 1703.01,2683.17 1710.01,2676.17 1710.01,2659.81 1717.01,2652.81 1749.01,2652.81 1954.72,2652.81 v1(1956.15,2654.24)
  SIG2 w6: v1(1956.15,2654.24) 1955,2655.38 1955,2739.32 1989.54,2773.86 1989.54,3298.27 1802.89,3484.92 1802.89,3852.65 1802.29,3853.25 1802.29,3968.1 1832.28,3998.08 1832.28,4120.29 1958.99,4247 2241.88,4247 2261.87,4266.99 v1(2261.87,4284)
  Bottom Layer w4: v1(2261.87,4284) 2261.87,4281.32 2255.21,4274.66 2255.21,4226.38 2342.07,4139.52 U29.U4@2342.07,4102.97
MSS_RGMII_RD2: R239.1 R286.1 R288.2 R338.1 U29.T4 | length 3166.2
  Top Layer w8: R338.1@1445.56,2718.89 1445.94,2718.51 1445.94,2710.12 1456.52,2699.53 v1(1456.52,2697.53) 1457.16,2698.17 1530.42,2698.17 1542.25,2710 1570.57,2710 1582.4,2698.17 1790.44,2698.17 1794.44,2698.17 1801.44,2705.17 1801.44,2739.18 1808.44,2746.18 1822.44,2746.18 1829.44,2739.18 1829.44,2676.54 1836.44,2669.54 1850.44,2669.54 1857.44,2676.54 1857.44,2733.92 1864.44,2740.92 1878.44,2740.92 1885.44,2733.92 1885.44,2705.31 1892.44,2698.31 1973.62,2698.42 1977.62,2698.43 v1(1978,2698.81)
  SIG2 w6: v1(1978,2698.81) 1978,2735.44 2006.54,2763.98 2006.54,3308.23 1819.89,3494.88 1819.89,3859.69 1819.29,3860.29 1819.29,3961.06 1849.28,3991.04 1849.28,4066.19 2013.09,4230 2255.69,4230 v1(2273.5,4247.81)
  Bottom Layer w4: v1(2273.5,4247.81) 2273.5,4231.87 2282.5,4222.87 2282.5,4212.95 2351.57,4143.88 2351.57,4127.7 2351.57,4117.38 2354.79,4114.16 2354.79,4090.1 U29.T4@2342.07,4077.38
  Bottom Layer w8: R286.1@1429.15,2707.26 1429.21,2707.19 1446.86,2707.19 v1(1456.52,2697.53) 1534.08,2697.53 1583.69,2647.93 R288.2@1583.69,2602.28
MSS_RGMII_RD3: R240.1 R339.1 U29.U5 | length 2950.6
  Top Layer w8: R339.1@1445.82,2761.09 1445.82,2745.12 1453.99,2736.95 1464.96,2736.95 1524.12,2736.95 1531.12,2743.95 1531.12,2761.67 1538.12,2768.67 1552.12,2768.67 1559.12,2761.67 1559.12,2743.95 1566.12,2736.95 1580.12,2736.95 1587.12,2743.95 1587.12,2761.67 1594.12,2768.67 1608.12,2768.67 1615.12,2761.67 1615.12,2743.95 1622.12,2736.95 1636.12,2736.95 1643.12,2743.95 1643.12,2761.54 1650.12,2768.54 1664.12,2768.54 1671.12,2761.54 1671.12,2743.95 1678.12,2736.95 1692.12,2736.95 1699.12,2743.95 1699.12,2761.54 1706.12,2768.54 1720.12,2768.54 1727.12,2761.54 1727.12,2743.95 1734.12,2736.95 1766.12,2736.95 1771,2736.95 1804.07,2770.02 2023.87,2770.02 2028.56,2765.34 2028.56,2746.25 2019.21,2736.9 v1(2019.21,2736.56)
  SIG2 w6: v1(2019.21,2736.56) 2019.21,2739.81 2024.1,2744.7 2024.1,3314.71 1838,3500.81 1838,3773.52 1873,3808.52 1873,3841.24 1836.29,3877.95 1836.29,3954.01 1866.28,3984 1866.28,4059.15 2020.13,4213 2262.73,4213 2272.54,4222.81 v1(2299.5,4222.81)
  Bottom Layer w4: v1(2299.5,4222.81) 2299.5,4209.39 2363.78,4145.11 2363.78,4118.39 ; 2363.78,4138.07 2363.78,4127.7 2363.78,4118.39 ; U29.U5@2367.66,4102.97 2366.34,4104.3 2366.34,4115.83 2363.78,4118.39
MSS_RGMII_TCLK: R74.1 R98.1 U29.T6 | length 471
  Bottom Layer w4: 2367.87,4307 2367.87,4206.81 2382.73,4191.96 2382.73,4172.08 2395.28,4159.53 2395.28,4141.02 2398.23,4138.07 2405.97,4130.33 2405.97,4090.1 U29.T6@2393.25,4077.38
  Bottom Layer w8: 2367.87,4307 2367.87,4320.52 2394.5,4347.14 2394.5,4494.31 2388.5,4500.31 R98.1@2375.03,4500.31
MSS_RGMII_TCTL: R101.1 R230.1 U29.U9 | length 412
  Bottom Layer w4: U29.U9@2470.03,4102.97 2470.03,4105.6 2473.89,4109.46 2473.89,4205.75 2470.24,4209.4 2470.24,4320.83 2472.4,4323
  Bottom Layer w8: R101.1@2454.42,4500.31 2455.34,4499.39 2460.83,4499.39 2472.4,4487.82 2472.4,4323
MSS_RGMII_TD0: R96.1 R103.1 U29.U7 | length 451.5
  Bottom Layer w4: 2381.37,4295 2380.38,4294 2380.38,4208.93 2392.23,4197.08 2392.23,4176.08 2404.78,4163.53 2404.78,4144.96 2408.66,4141.08 2418.84,4130.89 U29.U7@2418.84,4102.97
  Bottom Layer w8: 2381.37,4295 2381.37,4306.64 2434.19,4359.46 2434.19,4494.31 2430.67,4497.83 2428.19,4500.31 R103.1@2414.73,4500.31
MSS_RGMII_TD1: R100.1 R105.1 U29.U10 | length 436.9
  Bottom Layer w4: U29.U10@2495.62,4102.97 2495.62,4120.19 2484.5,4131.31 2484.5,4208.57 2479.74,4213.33 2479.74,4303.81 2495.61,4319.69
  Bottom Layer w8: R105.1@2494.11,4500.31 2510.5,4500.31 2515.19,4495.62 2515.19,4339.26 2495.61,4319.69
MSS_RGMII_TD2: R121.1 R178.1 U29.R12 | length 491.1
  Bottom Layer w4: U29.R12@2546.8,4051.79 2559.52,4064.51 2559.52,4127.7 2559.52,4138.07 2559.52,4168.16 2570.4,4179.04 2570.4,4299.13 2561.36,4308.16
  Bottom Layer w8: 2561.36,4308.16 2561.36,4404.17 2592.97,4435.78 2592.97,4494.31 2589.45,4497.83 2586.97,4500.31 R121.1@2573.5,4500.31
MSS_RGMII_TD3: R122.1 R225.1 U29.T12 | length 458
  Bottom Layer w4: 2533.8,4138.07 2533.93,4137.94 2533.93,4090.25 U29.T12@2546.8,4077.38
  Bottom Layer w8: 2533.8,4138.07 2533.04,4138.84 2533.04,4212.18 2527.34,4217.88 2527.34,4312.79 2542.53,4327.98 2542.53,4411.34 2553.5,4422.31 2553.5,4494.31 2547.5,4500.31 R122.1@2533.81,4500.31
MSS_RS232RX: R158.2 R278.1 U29.B19 | length 1901.8
  SIG1 w6: v1(1616,4020.81) 1742.27,4020.81 1836.39,3926.69 1836.39,3907.4 1964.41,3779.38 1964.41,3600.78 2028.46,3536.73 2185.15,3536.73 2232.35,3583.93 2384.99,3583.93 2408.93,3560 2625,3560 2630,3560 2655.69,3560 2754.44,3658.75 2755.69,3660 v1(2773.66,3660)
  Bottom Layer w4: U29.B19@2725.93,3719.11 2727.79,3717.25 2727.79,3709.65 2738.76,3698.68 2738.76,3677.33 2738.76,3675.74 2739.84,3674.59 2745.98,3668.05 2746.02,3668 2755.27,3658.75 2772.41,3658.75 v1(2773.66,3660) 2774.91,3658.75 2784.71,3648.95 2784.71,3584.91 R278.1@2788.54,3581.08
  Bottom Layer w8: R158.2@1498.67,4102.86 1498.67,4053.14 1531,4020.81 v1(1616,4020.81)
MSS_RS232TX: R162.2 R279.1 U29.A19 | length 2187.7
  SIG1 w6: v1(1217.86,3867.06) 1235.86,3885.06 1516.1,3885.06 1516.34,3884.81 1629.47,3884.81 2111.22,3403.05 2240.95,3403.05 2333,3311 2400.82,3311 2407.5,3317.68 2522.33,3317.68 2549.65,3345 2613.3,3345 2667.82,3399.52 2667.82,3548.24 2749.71,3630.13 2765.84,3630.13 v1(2767.71,3632)
  Bottom Layer w4: U29.A19@2725.93,3693.52 2725.93,3672.85 2766.78,3632 v1(2767.71,3632) 2767.71,3629.86 2753.42,3615.57 2753.42,3582.2 R279.1@2752.31,3581.08
  Bottom Layer w8: v1(1217.86,3867.06) R162.2@1217.86,3902.94
MSS_SPIA_CLK: R144.2 U29.T18 | length 2849.7
  SIG2 w6: v1(680.38,4465.4) 973.23,4758.26 1610.74,4758.26 1622.14,4746.86 1981,4746.86 2003.14,4769 2144.31,4769 2268.5,4644.81 2613,4644.81 2804,4453.81 v1(2804,4429.81)
  Bottom Layer w4: U29.T18@2700.34,4077.38 2713.1,4090.14 2713.1,4113.87 2732.31,4133.08 2732.31,4250.33 2755.62,4273.64 2761.65,4273.64 2804,4315.99
  Bottom Layer w8: v1(680.38,4465.4) R144.2@717.82,4465.4 ; 2804,4315.99 v1(2804,4429.81)
MSS_SPIA_CS0: R147.2 U29.U18 | length 2585.1
  Top Layer w8: v1(2786.59,4504.24) 2787.01,4504.65 2787.01,4721.08 v1(2787.42,4721.5)
  Bottom Layer w4: U29.U18@2700.34,4102.97 2700.78,4103.41 2700.78,4115.7 2722.81,4137.73 2722.81,4254.27 2751.68,4283.14 2757.72,4283.14 2784.74,4310.17 2784.74,4324
  Bottom Layer w8: R147.2@1006.27,4696.66 1006.27,4768.92 1071.35,4834 2618.97,4834 2731.47,4721.5 v1(2787.42,4721.5) ; 2784.74,4324 2784.74,4502.39 v1(2786.59,4504.24)
MSS_SPIA_HOSTIRQ: R109.1 R151.2 R153.2 R320.1 R326.2 | length 6832.8
  Top Layer w8: R320.1@760.24,1174.67 v1(786.39,1174.67)
  SIG1 w6: v1(840.35,3925) 1381.92,3925 1475.48,4018.56 1475.48,4432.04 v1(1523.27,4479.83)
  SIG2 w6: v1(786.39,1174.67) 647.14,1174.67 582.33,1239.48 582.33,1881.9 542.65,1921.59 542.65,1955.49 582.36,1995.2 695.86,1995.2 784.47,2083.81 1004.56,2083.81 1042.99,2122.24 1042.99,2827.22 1113,2897.23 1113,3003.32 1132.75,3023.07 1132.75,3067.56 1206,3140.81 1206,3270.84 1326.5,3391.34 1326.5,3767.07 1461.13,3901.7 1461.13,4417.69 v1(1523.27,4479.83) 1523.27,4556.08 1637.19,4670 1648.69,4670 1665.55,4686.86 1858.4,4686.86 1875.26,4670 2138.87,4670 2237.06,4571.81 2586.5,4571.81 2624.5,4533.81 2624.5,4448.19 v1(2637.88,4434.81)
  Bottom Layer w8: R151.2@1503.74,4531.01 1503.74,4479.83 v1(1523.27,4479.83)
  Bottom Layer w10.6: v1(2637.88,4434.81) 2639.88,4434.81 2655.97,4418.72 2663.85,4418.72 2668.4,4414.18 R326.2@2668.4,4412.21 R109.1@2668.4,4361.1
MSS_SPIA_MISO: R146.2 R392.1 | length 2869.4
  Bottom Layer w8: R146.2@954.15,4695.92 954.15,4778.3 1026.86,4851 2625.02,4851 2731.71,4744.31 2843.5,4744.31 3108.85,4478.96 3108.85,4093.12 3088.54,4072.81 R392.1@3054.95,4072.81
MSS_SPIA_MOSI: R145.2 U29.U17 | length 2688.8
  Top Layer w8: v1(2733.35,4473.52) 2734.17,4474.34 2734.17,4767.98 v1(2735,4768.81)
  Bottom Layer w4: U29.U17@2674.75,4102.97 2674.75,4117.42 2686.21,4128.88 2686.21,4138.07 2686.21,4151.18 2703.81,4168.78 2703.81,4272.62 2733.35,4302.16 2733.35,4316
  Bottom Layer w8: R145.2@900.95,4695.95 900.95,4784.98 983.27,4867.3 2636.51,4867.3 v1(2735,4768.81) ; 2733.35,4316 v1(2733.35,4473.52)
MSS_SPIB_CLK: R380.1 U26.2 | length 5452.1
  Top Layer w7.5: U26.2@1846.14,1133.04 1846.14,1108.09 1846.63,1107.6 v1(1846.63,1041.58)
  Top Layer w8: v1(1995.81,4286) 1994.15,4284.34 1994.15,4200.83 1928,4134.68 1928,3877.56 1910,3859.56 1910,3107.81 2315.65,2702.16 v1(2315.65,2267.4)
  SIG1 w6: v1(1995.81,4286) 2055.81,4346 2366.95,4346 2367.12,4345.83 2515.17,4345.83 2560.15,4390.81 v1(2583.89,4390.81)
  SIG2 w6: v1(1846.63,1041.58) 1846.63,1012.44 1819.34,985.15 1443.6,985.15 1315.44,1113.31 1315.44,1525.47 1323.93,1533.96 1340.89,1533.96 1341.46,1533.39 1566.61,1533.39 1627.32,1594.1 1848.11,1594.1 1940.84,1686.83 1940.84,1882.73 2253.37,2195.26 2253.37,2224.7 2280.82,2252.15 2300.4,2252.15 v1(2315.65,2267.4)
  Bottom Layer w8: R380.1@2583.89,4361.1 v1(2583.89,4390.81)
MSS_SPIB_CS0: R273.1 U26.10 U29.U15 | length 4534.6
  Top Layer w7.8: U26.10@1861.89,1196.03 1861.89,1294.7 v1(1937.48,1370.29)
  Top Layer w8: v1(2623.66,4295.81) 2731.66,4295.81 2758.14,4269.33 2813.65,4269.33 2838.87,4244.11 2838.87,4155.13 2887,4107 2925.19,4107 2983.26,4107 3059.26,4031 3084.6,4031 3093.6,4022 3162.82,4022 3197.04,3987.78 3197.04,3764.27 3160.84,3728.07 3160.84,3041.04 2834.8,2715 v1(2811.28,2715)
  SIG1 w6: v1(1937.48,1370.29) 2275,1707.81 2623.71,1707.81 2737.25,1821.35 2737.25,1880.55 2767,1910.3 2767,2670.52 2787.08,2690.6 2787.08,2690.8 v1(2811.28,2715)
  Bottom Layer w4: U29.U15@2623.57,4102.97 v1@2623.57,4295.72 ; v1(2623.66,4295.81) R273.1@2623.66,4321.73
MSS_SPIB_CS1: R107.1 R215.1 | length 5930.2
  Top Layer w8: v1(229,877.1) R215.1@251.34,877.1
  SIG2 w6: v1(229,877.1) 305.71,953.81 305.71,1838.63 618.03,2150.96 699.31,2150.96 770,2221.65 770,2705.03 897.28,2832.31 897.28,2844.68 929.6,2877 978,2877 986.47,2885.47 986.47,2921.2 885.28,3022.38 885.28,3433.28 1197,3745 1197,4041 1222,4066 1222,4305.88 1638.98,4722.86 1994.86,4722.86 2012,4740 2132.81,4740 2165.91,4706.91 2257.5,4615.31 2598.5,4615.31 2696.94,4516.87 v1(2696.94,4488.12)
  Bottom Layer w8: v1(2696.94,4488.12) 2696.94,4486.12 2709.06,4474 R107.1@2709,4361.1 R107.1@2709,4361.1
MSS_SPIB_MISO: U26.5 U29.T15 | length 4851.5
  Top Layer w8: U26.5@1901.26,1140.91 1918.6,1140.91 ; 1918.62,1140.88 1929.38,1140.88 v1(1944.28,1125.98) ; v1(2647,4385.81) 2718.38,4385.81 2853.87,4250.32 2853.87,4162.05 2893.92,4122 2925.19,4122 2992.53,4122 3068.53,4046 3090.81,4046 3099.81,4037 3172.87,4037 3212.04,3997.83 3212.04,3757.49 3176.45,3721.9 3176.45,3027.17 2756.34,2607.05 2756.34,2327.89 v1(2788.68,2295.55)
  SIG1 w6: v1(1944.28,1125.98) 1957.81,1139.51 1962.78,1139.51 1975.3,1127 2191.46,1127 2282.36,1217.9 2282.36,1276.36 2340,1334 2340,1619.51 2411.4,1690.91 2626.36,1690.91 2752.58,1817.13 2752.58,1877.36 2788.68,1913.46 v1(2788.68,2295.55)
  Bottom Layer w4: U29.T15@2623.57,4077.38 2636.29,4090.1 2636.29,4172.87 2633.29,4175.87 2633.29,4265.12 2647,4278.83 v1(2647,4385.81)
MSS_SPIB_MOSI: R381.1 U26.7 | length 3516.2
  Top Layer w8: U26.7@1901.26,1172.41 v1@1943.39,1172.41 ; v1(1947,4193.31) 1912,4158.31 1912,3883.11 1891,3862.11 1891,3094.81 2288.46,2697.35 v1(2288.46,2214.54)
  SIG2 w6: v1(1943.39,1170.13) 1961.39,1188.13 1961.39,1386.16 1993.6,1418.38 1993.6,1490.21 1975.02,1508.79 1975.02,1631.56 1966.52,1640.06 1966.52,1874.47 2287.35,2195.3 2287.35,2213.42 v1(2288.46,2214.54)
  Bottom Layer w8: v1(1947,4193.31) 2041.13,4193.31 R381.1@2043.63,4190.81
MSS_UARTA_RX: R129.1 U29.A16 | length 3781.1
  Top Layer w8: v1(2039.51,1145.19) 2066.98,1172.65 2448.42,1172.65 2474.26,1198.5 2590.79,1198.5 2684.48,1292.19 2774.81,1292.19 2814.64,1332.01 2814.64,1526.17 2776,1564.8 2572.01,1564.8 2468,1668.81 2468,1904.05 2707.42,2143.47 2707.42,2777.29 2879,2948.87 2879,3264.91 2658,3485.91 2658,3613.78 v1(2642.78,3629)
  Bottom Layer w8: v1(2039.51,1145.19) R129.1@2072.77,1145.19 ; v1(2642.78,3629) 2642.78,3652.8 2648.73,3658.75 2648.73,3661.86 2649.16,3662.29 U29.A16@2649.16,3693.52
NERR_MCU: R76.2 U8.16 | length 85.4
  Bottom Layer w8: R76.2@1328.61,1379.84 1356.95,1379.84 1377.81,1400.69 U8.16@1405.42,1400.69
NetC1_2: C1.2 C2.2 R37.2 U1.8 | length 160.7
  Bottom Layer w15: C1.2@2206.19,4571.73 2206.69,4572.23 2260.19,4572.23 C2.2@2260.69,4572.73 R37.2@2260.69,4626.23 2260.5,4626.04 2208.79,4626.04 U1.8@2208.6,4625.85
NetC11_2: C11.2 R16.1 U5.3 | length 108.6
  Bottom Layer w10: U5.3@786.62,503.91 R16.1@786.62,612.55
NetC13_2: C13.2 R15.1 R24.2 | length 289
  Top Layer w15: v1(507.42,311.94) v1(702.41,311.94)
  Bottom Layer w15: C13.2@478.49,311.94 v1(507.42,311.94) R15.1@542.39,311.94 ; R24.2@672.3,311.94 v1(702.41,311.94)
NetC14_1: C14.1 R26.2 U9.9 | length 126
  Bottom Layer w8: R26.2@934.47,954.77 948.66,940.58 948.66,913.95 948.66,910.02 C14.1@940.37,901.73 946.42,895.68 U9.9@946.42,840.58
NetC14_2: C14.2 R32.2 U9.10 | length 129.3
  Bottom Layer w8: U9.10@966.11,840.58 966.11,888.1 C14.2@979.74,901.73 972.72,908.76 972.72,912.69 972.72,939.99 973.14,939.99 R32.2@987.91,954.77
NetC16_2: C16.2 R78.1 U3.3 | length 111.1
  Bottom Layer w15: U3.3@1150.93,676.93 1150.93,705.54 1150.93,724.32 ; R78.1@1150.93,774.22 C16.2@1150.93,738.16 ; 1150.93,724.32 C16.2@1150.93,738.16 ; 1150.93,724.32 C16.2@1150.93,738.16
NetC17_1: C17.1 R47.2 U11.9 | length 133.6
  Bottom Layer w8: U11.9@1529.02,1968.16 1568.18,1968.16 C17.1@1595.68,1995.66
  Bottom Layer w10: C17.1@1595.68,1998.09 R47.2@1651.19,1998.09
NetC17_2: C17.2 R65.2 U11.10 | length 123
  Bottom Layer w8: U11.10@1529.02,1948.48 1595.62,1948.48 C17.2@1595.68,1948.41
  Bottom Layer w10: C17.2@1595.68,1948.41 1649.17,1948.41 R65.2@1651.19,1946.4
NetC19_1: C19.1 R348.2 U12.9 | length 134.6
  Top Layer w8: R348.2@2905.36,1913.98 2919.91,1928.54 2919.91,1954.74 C19.1@2906.73,1967.92 ; C19.1@2910.67,1967.92 2922.03,1979.28 U12.9@2922.03,2032.4
NetC19_2: C19.2 R352.2 U12.10 | length 132.8
  Top Layer w8: U12.10@2941.72,2032.4 2941.72,1976.24 C19.2@2950.04,1967.92 ; C19.2@2953.98,1967.92 2941.11,1955.05 2941.11,1927.95 R352.2@2954.95,1914.11
NetC21_1: C21.1 U2.2 | length 65.2
  Top Layer w8: C21.1@1799.66,450.16 U2.2@1864.88,450.16
NetC21_2: C21.2 L6.1 U2.1
NetC24_2: C24.2 R85.1 R87.2 | length 231.6
  Top Layer w15: v1(1066.12,290.61) v1(1185.75,290.6)
  Bottom Layer w10: C24.2@1006.26,317.57 R85.1@1066.12,317.57 v1@1066.12,291.51 ; v1@1185.75,291.5 R87.2@1185.75,317.57
NetC30_1: C30.1 R344.1 R414.1 Y4.2 | length 305.7
  Top Layer w8: R344.1@1083.65,2310.18 1077.03,2303.56 1077.03,2278.09 1094.62,2260.51 R414.1@1094.62,2249.26 1093.72,2249.26 1093.72,2246.47 1078.39,2231.15 1078.39,2207.69 1093.7,2192.39 1077.03,2175.72 1077.03,2104.02 1087.15,2093.9 Y4.2@1141.88,2093.9
NetC33_1: C33.1 R370.1 R414.2 Y4.1 | length 315.5
  Top Layer w8: Y4.1@980.46,2093.9 1044.15,2093.9 1053,2102.74 1053,2174.35 1034.96,2192.39 1052.57,2210 1052.57,2225.48 1035.57,2242.48 R414.2@1035.57,2249.26 1035.57,2257.13 1053.4,2274.97 1053.4,2303.7 R370.1@1046.92,2310.18
NetC34_2: C34.2 R293.1 R294.2 U16.2 | length 196.1
  Top Layer w10: U16.2@780.58,2989.96 780.58,2948.92 C34.2@798.3,2931.21 869.3,2931.21 R293.1@870.42,2932.33 R294.2@927.83,2932.33
NetC37_1: C37.1 C40.1 C44.1 C46.2 FB1.2 R50.2 R51.2 U4.22 | length 942.8
  Top Layer w15: v1(1113.52,3187.02) 1113.9,3187.4 R50.2@1143.2,3187.4
  PWR1 w15: v1(1113.52,3187.02) 1114.33,3187.02 1115.83,3188.52 1116.28,3188.52 1125.07,3197.31 1125.07,3223.5 1116,3232.57 1116,3263.32 1224.68,3372 1510.89,3372 1559.64,3323.25 1559.64,3242.99 v1(1560.21,3242.41)
  Bottom Layer w10: U4.22@1490.38,3167.25 1533.05,3167.25 1540.42,3174.62 1540.42,3186.94
  Bottom Layer w15: v1@1113.52,3187.4 R51.2@1143.2,3187.4 ; 1540.42,3186.94 1540.42,3222.62 v1(1560.21,3242.41) 1561.02,3242.41 1563.02,3240.41 C44.1@1604.58,3240.41 ; C44.1@1604.58,3242.41 C46.2@1604.58,3275.88
NetC51_1: C51.1 C52.1 C54.2 C122.1 R48.2 U4.11 | length 318.7
  Top Layer w15: C122.1@1203.47,3489.89 1203.47,3440.18 1206.32,3437.33 v1(1206.32,3436.52)
  Bottom Layer w10: U4.11@1317.15,3261.74 1317.15,3280.94
  Bottom Layer w15: v1(1206.32,3436.52) 1205.99,3436.19 1205.99,3336.34 C51.1@1205.67,3336.02 1210.59,3331.1 C54.2@1248.1,3331.1 C52.1@1284.68,3331.1 1317.15,3298.63 1317.15,3281.4
NetC71_2: C71.2 R154.1 U6.96 | length 250.7
  Bottom Layer w7: U6.96@2755.58,1710.31 2755.75,1710.48 2755.75,1737.87 2756.01,1738.13
  Bottom Layer w7.87: 2756.01,1738.13 2756.01,1738.56 2763.51,1746.06 2789.34,1746.06 2829.59,1705.81 2914.42,1705.81 C71.2@2918.92,1710.31 R154.1@2918.92,1672.6
NetC81_1: C81.1 R56.2 U22.9 | length 135
  Bottom Layer w8: R56.2@863.5,1558.62 881.7,1540.42 881.7,1519.02 C81.1@869.37,1506.69 877.55,1498.51 U22.9@877.55,1439.7
NetC81_2: C81.2 R66.2 U22.10 | length 137.6
  Bottom Layer w8: U22.10@897.24,1439.7 897.24,1491.25 912.67,1506.69 898.3,1521.06 898.3,1543.38 R66.2@913.54,1558.62
NetC86_1: C86.1 R181.1 U19.8 | length 180.5
  Top Layer w8: U19.8@1224.83,4141.24 C86.1@1224.83,4202.72 1248.1,4225.98 1293.08,4225.98 R181.1@1322.15,4196.91
NetC95_1: C95.1 R246.1 R248.2 Y5.1 | length 285.4
  Bottom Layer w8: Y5.1@899.95,3076.07 967.1,3076.07 1008.66,3117.63 1031.5,3140.47 1058.29,3140.47 C95.1@1070.29,3128.47 1070.29,3126.5 1075.98,3120.81 1077.95,3120.81 1092.76,3105.99 R246.1@1143.2,3105.99
NetC97_1: C97.1 R207.1 U21.6
NetC100_1: C100.1 D11.1 L5.1
NetC104_1: C104.1 C126.1 D3.2 D11.2 J12.1
NetC121_1: C121.1 R242.2 R248.1 R259.2 R367.2 Y5.2 | length 419.8
  Bottom Layer w8: R367.2@800.05,3238.13 899.31,3238.13 Y5.2@899.95,3237.49 1002.94,3237.49 1007.8,3232.63 R248.1@1007.8,3181.49 ; R248.1@1008.66,3180.63 1032.22,3157.07 1060.72,3157.07 C121.1@1070.29,3166.64 ; C121.1@1070.29,3167.47 1072.95,3164.81 1097.09,3164.81 1119.43,3142.47 R242.2@1143.2,3142.47
NetC123_2: C123.2 U8.18 | length 79.9
  Bottom Layer w8: C123.2@1335.09,1420.78 1335.09,1421.76 1346.84,1433.51 1347.83,1433.51 1348.19,1433.87 1363.18,1433.87 1369.37,1440.06 1377.61,1440.06 U8.18@1406.4,1440.06
NetC128_1: C128.1 R52.1 R55.2 SW3.4 | length 321.5
  Top Layer w8: SW3.4@57.15,454.37 57.15,420.12 72.8,404.47 R55.2@233.23,404.47 R52.1@233.23,458.31 C128.1@233.23,509.12
NetC149_2: C149.2 P1.2 U27.5
NetC155_2: C155.2 C156.1 R260.2 | length 71.7
  Bottom Layer w15: R260.2@1397.66,3618.51 C156.1@1434.69,3618.51 ; C155.2@1415.62,3652.92 1416.18,3652.35 1416.18,3618.51
NetC162_2: C162.2 C166.1 R274.1 | length 70.9
  Bottom Layer w15: R274.1@1397.66,3522.02 C162.2@1434.69,3522.02 ; C166.1@1416.18,3488.17 1416.18,3522.02
NetC167_1: C167.1 R275.1 R281.1 R282.2 | length 228.8
  Top Layer w25: R282.2@529.23,3615.44 R281.1@604.65,3615.44 R275.1@604.65,3525.09 C167.1@541.65,3525.09
NetD1_1: D1.1 R180.1 | length 63.8
  Top Layer w8: D1.1@1269.17,4556.1 1330.13,4556.1 R180.1@1332.18,4554.06
NetD2_1: D2.1 R36.2 | length 67.7
  Top Layer w8: R36.2@2195.53,1323.37 2224.81,1323.37 2237.59,1336.14 D2.1@2237.59,1356.5
NetD4_1: D4.1 R268.2 | length 56.9
  Top Layer w8: R268.2@64.98,1227 D4.1@64.98,1283.85
NetD5_1: D5.1 R362.2 | length 58.5
  Bottom Layer w8: D5.1@1600.48,4096.18 1600.48,4121.61 1606.54,4127.67 R362.2@1606.54,4152.19
NetD6_1: D6.1 R347.1 | length 60.8
  Top Layer w10: R347.1@3062.49,1992.48 D6.1@3062.49,2053.23
NetD7_1: D7.1 R108.1 | length 69.8
  Top Layer w8: R108.1@552.17,3086.52 D7.1@552.17,3156.33
NetD7_2: D7.2 R113.2 | length 69.8
  Top Layer w8: R113.2@493.11,3086.52 D7.2@493.11,3156.33
NetD8_1: D8.1 R120.2 | length 210.2
  Top Layer w8: D8.1@297.54,2111.42 498.1,2111.42 R120.2@504.92,2118.25
NetD9_1: D9.1 R261.1 | length 49.5
  Top Layer w15: D9.1@1400.32,4172.77 R261.1@1400.32,4222.31
NetD10_1: D10.1 R77.1 | length 76.5
  Top Layer w8: D10.1@1424,3009.09 1452.72,3009.09 1463.25,2998.56 R77.1@1463.25,2965.88 R77.1@1463.43,2965.7
NetD12_1: D12.1 R331.1 | length 99.8
  Top Layer w8: D12.1@2108.41,254.94 2147.34,293.88 R331.1@2147.34,338.61
NetD13_1: D13.1 R263.1 | length 38.7
  Top Layer w8: D13.1@262.47,1784.19 R263.1@262.47,1822.86
NetD13_2: D13.2 Q1.3 | length 69
  Top Layer w8: Q1.3@193.5,1719.23 D13.2@262.47,1719.23
NetD14_1: D14.1 R93.1 | length 50.3
  Top Layer w8: D14.1@1284.2,3091.95 R93.1@1284.2,3142.2
NetD16_1: D16.1 R332.1 | length 64.5
  Top Layer w8: R332.1@1082.76,845.49 D16.1@1082.76,910.02
NetDS2_1: DS2.1 R262.1 | length 50.1
  Top Layer w8: R262.1@1100.96,1379.84 DS2.1@1151.05,1379.84
NetJ7_10: J7.10 R320.2 | length 127.5
  Top Layer w8: J7.10@623.08,1135.3 678.93,1135.3 718.3,1174.67 R320.2@734.26,1174.67
NetJ7_13: J7.13 R418.1 | length 119.6
  Top Layer w8: R418.1@287.7,1119.56 311.32,1095.93 J7.13@397.49,1095.93
NetJ7_15: J7.15 R422.2 | length 121
  Top Layer w8: R422.2@278.9,1082.03 284.65,1076.28 J7.15@397.46,1076.28
NetJ7_16: J7.16 R115.2 | length 119.5
  Top Layer w8: J7.16@623.08,1076.25 687.79,1076.25 707.91,1096.36 R115.2@734.26,1096.36
NetJ7_17: J7.17 R423.2 | length 121.8
  Top Layer w8: R423.2@278.9,1050.53 278.9,1051.71 280.01,1052.83 281.2,1052.83 284.93,1056.56 J7.17@397.49,1056.56
NetJ7_20: J7.20 R424.1 | length 119.1
  Top Layer w8: J7.20@623.08,1036.88 679.16,1036.88 698.28,1056 R424.1@734.26,1056
NetJ7_22: J7.22 R425.1 | length 111.2
  Top Layer w8: J7.22@623.08,1017.19 R425.1@734.26,1017.19
NetJ7_41: J7.41 R328.2 | length 131.8
  Top Layer w8: R328.2@273.38,838.88 297.93,838.88 316.47,820.34 J7.41@397.49,820.34
NetJ7_43: J7.43 R329.2 | length 122.1
  Top Layer w8: R329.2@275.35,800.66 J7.43@397.49,800.66
NetJ7_55: J7.55 R197.2 | length 131.7
  Top Layer w8: R197.2@275.33,659.45 298.15,659.45 321.24,682.55 J7.55@397.49,682.55
NetJ7_57: J7.57 R198.2 | length 136.6
  Top Layer w8: R198.2@275.33,627.95 298.15,627.95 333.05,662.86 J7.57@397.49,662.86
NetJ7_59: J7.59 R114.2 | length 141.5
  Top Layer w8: R114.2@275.33,596.46 300.32,596.46 347.04,643.18 J7.59@397.49,643.18
NetJ8_1: J8.1 R161.1 | length 101.9
  Bottom Layer w15: R161.1@3094.42,1585.36 3126.37,1553.41 J8.1@3183.06,1553.41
